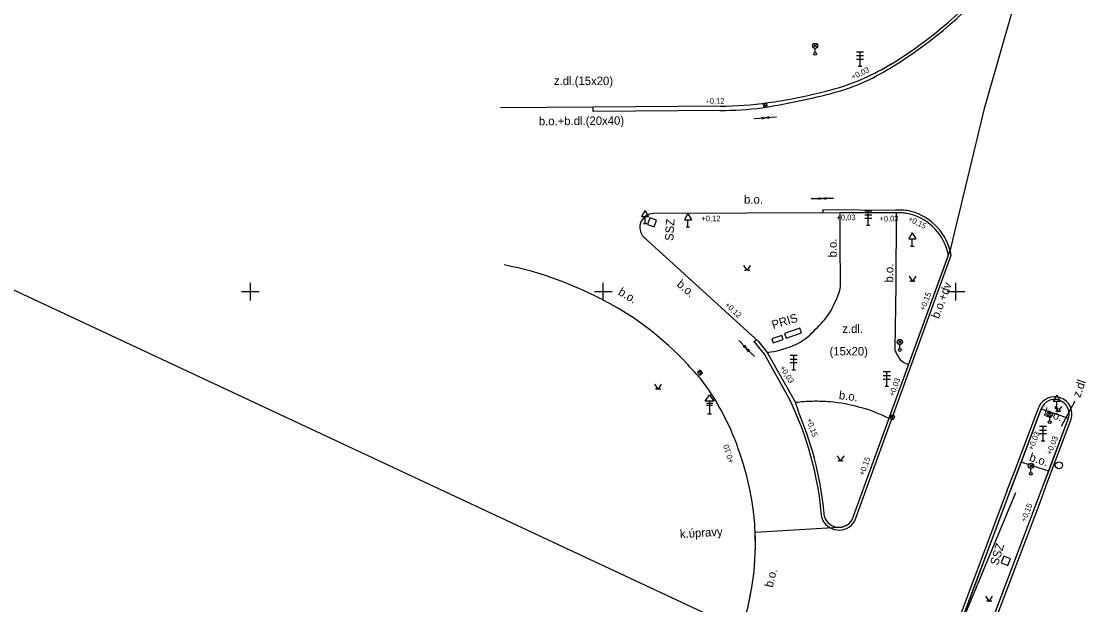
# Model space of a CAD drawing. Extents: x -599151 to -598424, y -1163476 to -1161924.
# Drawn here: x -598766.2 to -598690.8, y -1162672.2 to -1162630.9 of the extents above; entities that cross this region are included whole.
import ezdxf

# ---------------------------------------------------------------- set-up
doc = ezdxf.new("R2010")
doc.units = 0
for name, color, linetype in [('Vrstva 1', 7, 'Continuous'), ('Vrstva 14', 7, 'Continuous'), ('Vrstva 19', 7, 'Continuous'), ('Vrstva 21', 7, 'Continuous'), ('Vrstva 23', 7, 'Continuous'), ('Vrstva 25', 7, 'Continuous'), ('Vrstva 29', 7, 'Continuous'), ('Vrstva 44', 7, 'Continuous'), ('Vrstva 49', 7, 'Continuous'), ('Vrstva 50', 7, 'Continuous'), ('Vrstva 62', 7, 'Continuous'), ('Vrstva 63', 7, 'Continuous'), ('Vrstva 7', 7, 'Continuous')]:
    doc.layers.add(name, color=color, linetype=linetype)

msp = doc.modelspace()

# ---------------------------------------------------------------- linework, layer by layer
at = {"layer": 'Vrstva 1'}
msp.add_line((-598707.361, -1162677.641), (-598774.638, -1162646.226), dxfattribs=at)
at = {"layer": 'Vrstva 14'}
for points in [[(-598715.053, -1162648.14), (-598714.803, -1162648.515), (-598714.553, -1162648.14)], [(-598703.325, -1162648.904), (-598703.075, -1162649.279), (-598702.825, -1162648.904)], [(-598721.363, -1162656.546), (-598721.113, -1162656.921), (-598720.863, -1162656.546)], [(-598693.002, -1162658.128), (-598692.752, -1162658.503), (-598692.502, -1162658.128)], [(-598708.424, -1162661.641), (-598708.174, -1162662.016), (-598707.924, -1162661.641)], [(-598697.903, -1162671.563), (-598697.653, -1162671.938), (-598697.403, -1162671.563)]]:
    msp.add_lwpolyline(points, dxfattribs=at)
for centre in [(-598714.928, -1162648.49), (-598714.678, -1162648.49), (-598703.2, -1162649.254), (-598702.95, -1162649.254), (-598721.238, -1162656.896), (-598720.988, -1162656.896), (-598692.877, -1162658.478), (-598692.627, -1162658.478), (-598708.299, -1162661.991), (-598708.049, -1162661.991), (-598697.778, -1162671.913), (-598697.528, -1162671.913)]:
    msp.add_circle(centre, 0.025, dxfattribs=at)
at = {"layer": 'Vrstva 19'}
for p, q in [((-598706.55, -1162633.03), (-598707.05, -1162633.03)), ((-598706.8, -1162634.03), (-598706.8, -1162633.03)), ((-598707.05, -1162633.28), (-598706.55, -1162633.28)), ((-598707.05, -1162633.53), (-598706.55, -1162633.53)), ((-598706.925, -1162634.03), (-598706.675, -1162634.03)), ((-598722.03, -1162644.248), (-598722.28, -1162644.681)), ((-598722.03, -1162644.248), (-598721.78, -1162644.681)), ((-598705.97, -1162644.3), (-598706.47, -1162644.3)), ((-598706.22, -1162645.3), (-598706.22, -1162644.3)), ((-598722.28, -1162644.681), (-598721.78, -1162644.681)), ((-598722.03, -1162645.181), (-598722.03, -1162644.681)), ((-598719, -1162644.478), (-598719.25, -1162644.911)), ((-598719.25, -1162644.911), (-598718.75, -1162644.911)), ((-598719, -1162644.478), (-598718.75, -1162644.911)), ((-598719, -1162645.411), (-598719, -1162644.911)), ((-598706.47, -1162644.55), (-598705.97, -1162644.55)), ((-598706.47, -1162644.8), (-598705.97, -1162644.8)), ((-598722.155, -1162645.181), (-598721.905, -1162645.181)), ((-598719.125, -1162645.411), (-598718.875, -1162645.411)), ((-598706.345, -1162645.3), (-598706.095, -1162645.3)), ((-598703.1, -1162645.837), (-598703.35, -1162646.27)), ((-598703.1, -1162645.837), (-598702.85, -1162646.27)), ((-598703.35, -1162646.27), (-598702.85, -1162646.27)), ((-598703.1, -1162646.77), (-598703.1, -1162646.27)), ((-598703.225, -1162646.77), (-598702.975, -1162646.77)), ((-598711.25, -1162654.53), (-598711.75, -1162654.53)), ((-598711.75, -1162654.78), (-598711.25, -1162654.78)), ((-598711.5, -1162655.53), (-598711.5, -1162654.53)), ((-598711.75, -1162655.03), (-598711.25, -1162655.03)), ((-598711.625, -1162655.53), (-598711.375, -1162655.53)), ((-598704.65, -1162655.69), (-598705.15, -1162655.69)), ((-598705.15, -1162655.94), (-598704.65, -1162655.94)), ((-598705.15, -1162656.19), (-598704.65, -1162656.19)), ((-598704.9, -1162656.69), (-598704.9, -1162655.69)), ((-598705.025, -1162656.69), (-598704.775, -1162656.69)), ((-598692.86, -1162657.327), (-598693.11, -1162657.76)), ((-598693.11, -1162657.76), (-598692.61, -1162657.76)), ((-598692.86, -1162657.327), (-598692.61, -1162657.76)), ((-598692.86, -1162658.26), (-598692.86, -1162657.76)), ((-598692.985, -1162658.26), (-598692.735, -1162658.26)), ((-598693.58, -1162659.56), (-598694.08, -1162659.56)), ((-598694.08, -1162659.81), (-598693.58, -1162659.81)), ((-598694.08, -1162660.06), (-598693.58, -1162660.06)), ((-598693.83, -1162660.56), (-598693.83, -1162659.56)), ((-598693.955, -1162660.56), (-598693.705, -1162660.56))]:
    msp.add_line(p, q, dxfattribs=at)
at = {"layer": 'Vrstva 21'}
msp.add_lwpolyline([(-598695.78, -1162664.24), (-598699.97, -1162674.3), (-598702.11, -1162679.97), (-598709.91, -1162700.89), (-598717.13, -1162720.74), (-598723.5, -1162738.84), (-598727.94, -1162752.59), (-598729.98, -1162757.92), (-598744.45, -1162796.07), (-598751.7, -1162815.01), (-598765.52, -1162851.41), (-598773.26, -1162871.58), (-598779.91, -1162889.88), (-598781.91, -1162894.82), (-598784.85, -1162901.68), (-598795.29, -1162929.3), (-598803.04, -1162949.86), (-598814.6, -1162980.19)], dxfattribs=at)
at = {"layer": 'Vrstva 23'}
for p, q in [((-598721.694, -1162644.77), (-598721.865, -1162645.239)), ((-598721.225, -1162644.941), (-598721.694, -1162644.77)), ((-598721.396, -1162645.41), (-598721.225, -1162644.941)), ((-598721.865, -1162645.239), (-598721.396, -1162645.41)), ((-598696.616, -1162668.748), (-598696.792, -1162669.216)), ((-598696.792, -1162669.216), (-598696.324, -1162669.392)), ((-598696.148, -1162668.924), (-598696.616, -1162668.748)), ((-598696.324, -1162669.392), (-598696.148, -1162668.924))]:
    msp.add_line(p, q, dxfattribs=at)
at = {"layer": 'Vrstva 25'}
for p, q in [((-598713.644, -1162636.839), (-598713.396, -1162636.801)), ((-598718.233, -1162655.636), (-598718.067, -1162655.824)), ((-598704.544, -1162659.024), (-598704.458, -1162658.79))]:
    msp.add_line(p, q, dxfattribs=at)
for points in [[(-598713.624, -1162636.963), (-598713.377, -1162636.924), (-598713.416, -1162636.677), (-598713.663, -1162636.716)], [(-598718.326, -1162655.719), (-598718.161, -1162655.906), (-598717.974, -1162655.741), (-598718.139, -1162655.554)], [(-598704.426, -1162659.067), (-598704.341, -1162658.832), (-598704.576, -1162658.747), (-598704.661, -1162658.982)]]:
    msp.add_lwpolyline(points, close=True, dxfattribs=at)
msp.add_circle((-598692.71, -1162662.3), 0.25, dxfattribs=at)
at = {"layer": 'Vrstva 29'}
for p, q in [((-598710.112, -1162632.72), (-598709.848, -1162632.456)), ((-598709.844, -1162632.719), (-598710.108, -1162632.454)), ((-598709.98, -1162633.051), (-598709.98, -1162632.776)), ((-598704.112, -1162653.7), (-598703.848, -1162653.436)), ((-598703.844, -1162653.699), (-598704.108, -1162653.434)), ((-598703.98, -1162654.031), (-598703.98, -1162653.756)), ((-598693.492, -1162658.819), (-598693.228, -1162658.555)), ((-598693.224, -1162658.818), (-598693.488, -1162658.553)), ((-598693.36, -1162659.15), (-598693.36, -1162658.875)), ((-598694.822, -1162662.469), (-598694.558, -1162662.205)), ((-598694.554, -1162662.468), (-598694.818, -1162662.203)), ((-598694.69, -1162662.8), (-598694.69, -1162662.525))]:
    msp.add_line(p, q, dxfattribs=at)
for points in [[(-598712.04, -1162653.291), (-598710.94, -1162652.911), (-598711.054, -1162652.58), (-598712.154, -1162652.96)], [(-598712.96, -1162653.631), (-598712.24, -1162653.391), (-598712.335, -1162653.106), (-598713.055, -1162653.346)]]:
    msp.add_lwpolyline(points, close=True, dxfattribs=at)
for centre, radius in [((-598709.98, -1162632.589), 0.188), ((-598709.98, -1162633.151), 0.1), ((-598703.98, -1162653.569), 0.188), ((-598703.98, -1162654.131), 0.1), ((-598693.36, -1162658.688), 0.188), ((-598693.36, -1162659.25), 0.1), ((-598694.69, -1162662.338), 0.188), ((-598694.69, -1162662.9), 0.1)]:
    msp.add_circle(centre, radius, dxfattribs=at)
at = {"layer": 'Vrstva 44'}
for p, q in [((-598717.69, -1162657.901), (-598717.242, -1162657.901)), ((-598717.47, -1162657.751), (-598717.47, -1162658.651)), ((-598717.69, -1162658.051), (-598717.247, -1162658.051)), ((-598717.62, -1162658.651), (-598717.32, -1162658.651))]:
    msp.add_line(p, q, dxfattribs=at)
msp.add_lwpolyline([(-598717.77, -1162657.756), (-598717.47, -1162657.301), (-598717.17, -1162657.756)], close=True, dxfattribs=at)
at = {"layer": 'Vrstva 49'}
for p, q in [((-598714.292, -1162637.741), (-598713.501, -1162637.693)), ((-598713.775, -1162637.639), (-598713.501, -1162637.693)), ((-598713.501, -1162637.693), (-598713.766, -1162637.783)), ((-598713.501, -1162637.693), (-598713.236, -1162637.603)), ((-598712.71, -1162637.645), (-598713.501, -1162637.693)), ((-598713.228, -1162637.749), (-598713.501, -1162637.693)), ((-598710.269, -1162643.412), (-598709.477, -1162643.412)), ((-598709.747, -1162643.341), (-598709.477, -1162643.412)), ((-598709.477, -1162643.412), (-598709.747, -1162643.486)), ((-598709.477, -1162643.412), (-598709.207, -1162643.339)), ((-598708.685, -1162643.412), (-598709.477, -1162643.412)), ((-598709.208, -1162643.484), (-598709.477, -1162643.412)), ((-598715.397, -1162653.456), (-598714.843, -1162654.022)), ((-598714.843, -1162654.022), (-598715.085, -1162653.881)), ((-598714.981, -1162653.78), (-598714.843, -1162654.022)), ((-598714.289, -1162654.588), (-598714.843, -1162654.022)), ((-598714.706, -1162654.264), (-598714.843, -1162654.022)), ((-598714.843, -1162654.022), (-598714.602, -1162654.164)), ((-598692.515, -1162659.525), (-598691.552, -1162657.746))]:
    msp.add_line(p, q, dxfattribs=at)
at = {"layer": 'Vrstva 62'}
for p, q in [((-598750, -1162650.625), (-598750, -1162649.375)), ((-598725, -1162650.625), (-598725, -1162649.375)), ((-598700, -1162650.625), (-598700, -1162649.375)), ((-598750.625, -1162650), (-598749.375, -1162650)), ((-598725.625, -1162650), (-598724.375, -1162650)), ((-598700.625, -1162650), (-598699.375, -1162650))]:
    msp.add_line(p, q, dxfattribs=at)
at = {"layer": 'Vrstva 63'}
for points in [[(-598700.368, -1162646.938), (-598697.95, -1162636.94), (-598695, -1162626.61), (-598693.096, -1162620.604), (-598693.285, -1162620.54)], [(-598707.36, -1162666.16), (-598700.368, -1162646.938)], [(-598859.45, -1163096.65), (-598854.32, -1163084.15), (-598824.47, -1163005.5), (-598816.67, -1162984.98), (-598803.24, -1162949.74), (-598780.23, -1162889.28), (-598773.478, -1162871.463), (-598765.88, -1162851.33), (-598758.84, -1162832.8), (-598745.6, -1162798.16), (-598737.25, -1162776.15), (-598728.25, -1162752.5), (-598723.5, -1162738.84), (-598717.13, -1162720.74), (-598709.91, -1162700.89), (-598702.11, -1162679.97), (-598696.15, -1162664.13), (-598695.39, -1162662.07), (-598693.97, -1162658.31)], [(-598713.47, -1162715.62), (-598708.12, -1162701.56), (-598694.22, -1162664.8), (-598692.03, -1162658.97)], [(-598714.23, -1162667.03), (-598708.33, -1162666.69)]]:
    msp.add_lwpolyline(points, dxfattribs=at)
for centre, radius, start, end in [((-598693.009, -1162658.667), 1.025, 342.81919, 159.60356), ((-598708.292, -1162665.607), 1.084, 267.99015, 329.31351), ((-598733.303, -1162667.848), 19.091, 338.83707, 2.45527)]:
    msp.add_arc(centre, radius, start, end, dxfattribs=at)
at = {"layer": 'Vrstva 7'}
for p, q in [((-598713.504, -1162636.937), (-598713.543, -1162636.647)), ((-598725.708, -1162637.241), (-598725.711, -1162636.94)), ((-598709.44, -1162644.179), (-598709.439, -1162644.429)), ((-598721.979, -1162646.255), (-598721.856, -1162646.368)), ((-598721.856, -1162646.368), (-598713.99, -1162653.531)), ((-598714.325, -1162653.563), (-598714.144, -1162653.39)), ((-598713.99, -1162653.531), (-598713.37, -1162654.301)), ((-598713.37, -1162654.301), (-598711.37, -1162657.86))]:
    msp.add_line(p, q, dxfattribs=at)
for points in [[(-598706.862, -1162635.304), (-598706.757, -1162635.259), (-598706.225, -1162635.021), (-598706.131, -1162634.977)], [(-598716.72, -1162636.87), (-598725.711, -1162636.94), (-598732.29, -1162636.991)], [(-598716.717, -1162637.171), (-598725.708, -1162637.241)], [(-598709.44, -1162644.179), (-598704.254, -1162644.23)], [(-598704.24, -1162644.43), (-598708.21, -1162644.424), (-598721.433, -1162644.471)], [(-598708.18, -1162649.441), (-598708.197, -1162646.528), (-598708.21, -1162644.424)], [(-598704.24, -1162644.43), (-598704.273, -1162649.53), (-598704.33, -1162654.06)], [(-598707.36, -1162666.16), (-598700.54, -1162647.41)], [(-598707.178, -1162666.246), (-598700.333, -1162647.427)], [(-598711.826, -1162657.566), (-598713.578, -1162654.441), (-598714.172, -1162653.702), (-598714.325, -1162653.563)], [(-598696.37, -1162664.06), (-598695.83, -1162662.7), (-598694.138, -1162658.191)], [(-598693.97, -1162658.31), (-598695.39, -1162662.07), (-598695.73, -1162663), (-598696.15, -1162664.13)], [(-598693.97, -1162658.31), (-598692.03, -1162658.97)], [(-598694.22, -1162664.8), (-598693.8, -1162663.66), (-598693.43, -1162662.72), (-598692.03, -1162658.97)], [(-598694, -1162664.87), (-598693.613, -1162663.731), (-598693.243, -1162662.792), (-598691.839, -1162659.029)], [(-598693.43, -1162662.72), (-598695.39, -1162662.07)], [(-598696.37, -1162664.06), (-598702.36, -1162680), (-598710.16, -1162700.82), (-598717.38, -1162720.66), (-598723.7, -1162738.77), (-598728.46, -1162752.352), (-598730.54, -1162757.75), (-598737.46, -1162776.08), (-598745, -1162795.86), (-598752.22, -1162814.82), (-598759.04, -1162832.74), (-598766.06, -1162851.25)], [(-598765.88, -1162851.33), (-598758.84, -1162832.8), (-598752, -1162814.9), (-598745.6, -1162798.16), (-598744.77, -1162795.95), (-598742.6, -1162790.26), (-598740.02, -1162783.45), (-598737.25, -1162776.15), (-598730.28, -1162757.84), (-598728.25, -1162752.5), (-598723.5, -1162738.84), (-598717.13, -1162720.74), (-598709.91, -1162700.89), (-598702.11, -1162679.97), (-598699.97, -1162674.3), (-598696.15, -1162664.13)], [(-598762.5, -1162853.02), (-598755.36, -1162834.29), (-598748.57, -1162816.46), (-598741.19, -1162797.06), (-598733.81, -1162777.57), (-598727.52, -1162758.45), (-598721.48, -1162740.08), (-598715.31, -1162721.42), (-598707.94, -1162701.65), (-598699.86, -1162680.28), (-598694, -1162664.87)], [(-598713.47, -1162715.62), (-598708.12, -1162701.56), (-598700.05, -1162680.2), (-598694.22, -1162664.8)]]:
    msp.add_lwpolyline(points, dxfattribs=at)
for centre, radius, start, end in [((-598720.873, -1162607.404), 31.087, 301.4995, 320.11107), ((-598720.873, -1162607.404), 31.287, 301.4995, 320.1146), ((-598715.205, -1162615.638), 21.111, 294.32558, 300.35639), ((-598715.721, -1162615.91), 21.343, 296.70118, 301.63783), ((-598706.21, -1162631.158), 3.166, 300.35639, 300.35752), ((-598712.472, -1162621.815), 14.357, 287.05968, 294.53885), ((-598712.24, -1162622.397), 13.983, 286.84641, 292.61683), ((-598718.731, -1162598.604), 38.395, 279.44683, 284.3572), ((-598722.62, -1162581.483), 56.199, 280.96346, 283.87077), ((-598718.305, -1162600.261), 36.684, 284.35503, 285.30614), ((-598718.305, -1162600.261), 36.934, 284.35503, 285.30614), ((-598712.314, -1162622.152), 13.988, 285.30614, 286.84641), ((-598712.314, -1162622.152), 14.238, 285.30614, 286.84641), ((-598716.916, -1162611.353), 25.519, 270.44158, 278.10874), ((-598722.63, -1162581.44), 56.242, 279.08328, 280.96481), ((-598719.153, -1162595.883), 41.149, 278.15303, 279.40472), ((-598716.916, -1162611.353), 25.819, 270.44158, 277.04199), ((-598704.007, -1162647.804), 3.582, 76.84099, 93.95623), ((-598704.213, -1162648.122), 3.941, 10.16539, 74.98079), ((-598721.43, -1162645.448), 0.977, 90.20022, 235.76878), ((-598704.007, -1162647.804), 3.382, 76.89593, 93.95623), ((-598704.213, -1162648.122), 3.741, 10.97818, 74.931), ((-598736.91, -1162673.037), 25.403, 61.23104, 78.87857), ((-598710.115, -1162649.452), 1.935, 339.41333, 0.34172), ((-598716.596, -1162647.018), 8.858, 329.67379, 339.41333), ((-598735.023, -1162669.954), 21.794, 43.07901, 61.67923), ((-598711.638, -1162649.918), 3.114, 318.29814, 329.67378), ((-598722.617, -1162640.135), 17.82, 313.54935, 318.29814), ((-598713.017, -1162650.234), 3.886, 292.41817, 313.54934), ((-598714.155, -1162647.475), 6.871, 276.56605, 292.41817), ((-598703.961, -1162654.065), 0.369, 179.28755, 203.87528), ((-598700.672, -1162652.609), 3.966, 203.87528, 211.31878), ((-598703.282, -1162654.197), 0.911, 211.31877, 235.28606), ((-598797.713, -1162728.386), 107.493, 42.28471, 43.00497), ((-598702.87, -1162653.603), 1.634, 235.28606, 253.1204), ((-598719.046, -1162656.844), 1.16, 38.60548, 42.3458), ((-598729.495, -1162665.187), 14.53, 29.70211, 38.60548), ((-598732.899, -1162667.868), 23.457, 4.59458, 26.05366), ((-598709.913, -1162669.369), 11.6, 91.17393, 97.21234), ((-598737.89, -1162667.295), 28.148, 17.67194, 19.58378), ((-598709.913, -1162669.369), 11.6, 85.13552, 91.17393), ((-598709.913, -1162669.369), 11.6, 74.32718, 85.13552), ((-598693.009, -1162658.667), 1.225, 342.81916, 157.14174), ((-598693.009, -1162658.667), 1.025, 342.81919, 159.60357), ((-598735.52, -1162668.624), 21.467, 22.37955, 29.70211), ((-598709.913, -1162669.369), 11.6, 63.51884, 74.32718), ((-598732.899, -1162667.868), 23.657, 4.65106, 22.67125), ((-598721.761, -1162662.959), 6.587, 20.22486, 22.37955), ((-598777.745, -1162682.391), 65.847, 18.5529, 19.25076), ((-598733.303, -1162667.848), 19.091, 338.83707, 19.61216), ((-598708.292, -1162665.607), 1.284, 197.32754, 330.1633), ((-598708.292, -1162665.607), 1.084, 198.45548, 329.31351)]:
    msp.add_arc(centre, radius, start, end, dxfattribs=at)

# ---------------------------------------------------------------- texts
at = {"layer": 'Vrstva 49'}
for s, height, rotation, p in [('z.dl.(15x20)', 0.59999, 359.84578, (-598728.494, -1162635.365)), ('b.o.+b.dl.(20x40)', 0.6, 0.44158, (-598729.562, -1162638.224)), ('SSZ', 0.6, 86.62508, (-598720.032, -1162646.42)), ('b.o.', 0.6, 89.62927, (-598708.457, -1162647.583)), ('b.o.', 0.6, 89.62927, (-598704.447, -1162649.36)), ('b.o.', 0.6, 319.48272, (-598719.837, -1162649.558)), ('b.o.+dv', 0.6, 69.39238, (-598701.219, -1162651.962)), ('b.o.', 0.6, 329.30415, (-598723.987, -1162650.186)), ('PRIS', 0.6, 17.18799, (-598712.948, -1162652.663)), ('z.dl', 0.6, 70.83404, (-598691.199, -1162657.554)), ('b.o.', 0.6, 352.74741, (-598708.324, -1162657.606)), ('b.o.', 0.6, 341.65279, (-598693.826, -1162658.776)), ('b.o.', 0.6, 341.65279, (-598694.852, -1162661.969)), ('k.úpravy', 0.6, 3.29814, (-598719.548, -1162667.46)), ('SSZ', 0.6, 73.08551, (-598697.026, -1162669.431)), ('b.o.', 0.6, 75.69642, (-598712.999, -1162670.999))]:
    msp.add_text(s, height=height, rotation=rotation, dxfattribs=at).set_placement(p)
for s, p in [('b.o.', (-598715.018, -1162643.772)), ('z.dl.', (-598708.057, -1162652.929)), ('(15x20)', (-598708.962, -1162654.52))]:
    msp.add_text(s, height=0.6, dxfattribs=at).set_placement(p)
at = {"layer": 'Vrstva 50'}
for s, rotation, p in [('+0,03', 26.10342, (-598707.303, -1162635.009)), ('+0,12', 0.44607, (-598717.76, -1162636.704)), ('+0,12', 0.44607, (-598718.04, -1162645.027)), ('+0,03', 0.77986, (-598708.466, -1162644.954)), ('+0,03', 0.77986, (-598705.425, -1162645.039)), ('+0,15', 334.74763, (-598703.437, -1162644.992)), ('+0,15', 69.39238, (-598702.212, -1162651.395)), ('+0,12', 317.67813, (-598716.412, -1162650.991)), ('+0,03', 301.52291, (-598712.497, -1162655.389)), ('+0,03', 69.39238, (-598704.407, -1162657.468)), ('+0,15', 288.75484, (-598710.6, -1162659.045)), ('+0,03', 69.52772, (-598694.533, -1162661.274)), ('+0,10', 106.84124, (-598715.727, -1162662.08)), ('+0,03', 69.52772, (-598693.233, -1162661.59)), ('+0,15', 69.39238, (-598706.521, -1162663.065)), ('+0,15', 68.74567, (-598695.058, -1162666.353))]:
    msp.add_text(s, height=0.4, rotation=rotation, dxfattribs=at).set_placement(p)

doc.saveas('drawing.dxf')
